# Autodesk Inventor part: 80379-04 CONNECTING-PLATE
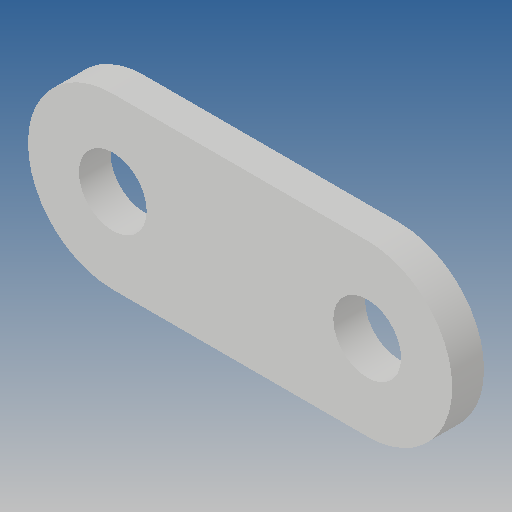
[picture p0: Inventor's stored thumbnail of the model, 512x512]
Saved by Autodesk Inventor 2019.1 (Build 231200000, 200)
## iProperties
Created: 2012-10
Part Number: 80379-04 CONNECTING-PLATE
Material: Ogólny
Document SubType Name: Modeling
Designer: CADENGINEERING4
Density: 1 g/cm^3
Appearance: Domyślna
Author: CADENGINEERING4
Revision Number: ÈÎºÎ
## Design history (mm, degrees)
feature "À­Éì1"
node "Bryła1"
